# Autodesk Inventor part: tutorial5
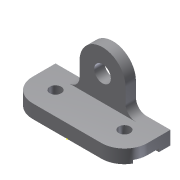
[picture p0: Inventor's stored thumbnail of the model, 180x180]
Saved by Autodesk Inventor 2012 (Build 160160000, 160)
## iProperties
Created: 2011-03
Part Number: tutorial5
Material: Default
Document SubType Name: Modeling
Designer: CadCim
Density: 1 g/cm^3
Author: CadCim
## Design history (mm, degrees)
sketch "Sketch1"
  geometry: 1 further point
sketch "Sketch2"
  geometry: L1 (0, 0)-(0, 13); L2 (0, 13)-(44, 13); L3 (44, 13)-(44, 0); L4 (44, 0)-(33, 0); L5 (33, 0)-(33, 3); L6 (33, 3)-(11, 3); L7 (11, 3)-(11, 0); L8 (11, 0)-(0, 0); 1 further point
  constraints: 16 end point, 4 parallel, 4 perpendicular, 1 coincident, 1 vertical
  dimensions: "d0" = 13 distance of L1.start L1.end; "d1" = 44 distance of L1.end L2.end; "d2" = 11 distance of L3.end L4.end; "d3" = 3 distance of L4.end L5.end; "d4" = 22 distance of L5.end L6.end
extrude "Extrusion1" new body sketch "Sketch2" stored distance "d6" = 110; taper "d7" = 0 deg
fillet "Fillet1" dims "d8" = 22
mirror "Mirror1"
sketch "Sketch3"
  geometry: L1 (77, -13)-(77, -37); L2 (33, -37)-(33, -13); L3 (77, -13)-(33, -13); L4 (110, 0)-(0, 0) reference; C1 r 8 at (55, -37); A1 r 22 centre (55, -37) between (33, -37) and (77, -37); 1 further point
  constraints: 6 end point, 2 centre point, 2 point on circle, 2 tangent, 1 coincident, 1 parallel, 1 perpendicular
  dimensions: "d9" = 37 distance from line of L4 A1.centre; "d10" = 55 horizontal distance of L4.end A1.centre; "d11" = 22 radius of A1; "d12" = 16 diameter of C1
extrude "Extrusion2" join sketch "Sketch3" distance "d13" = 10; taper "d14" = 0 deg
fillet "Fillet2" dims "d15" = 10
mirror "Mirror2"
hole "Hole1" diameter "d18" = 11; stored, may be unused: countersink angle "d22" = 90 deg, drill point angle "d24" = 118 deg; dims "d16" = 10, "d17" = 10, "d19" = 6, "d20" = 4, "d21" = 2, "d23" = 8
mirror "Mirror3"
body "Solid1"
